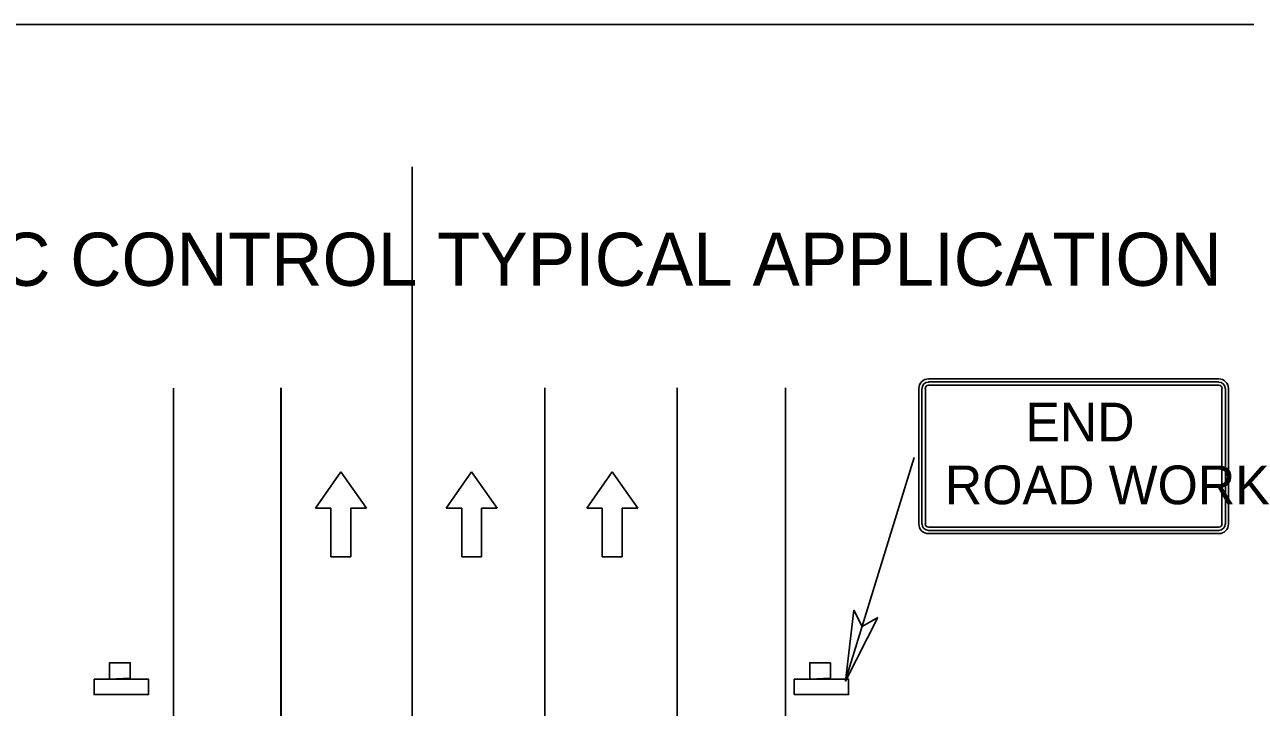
# Model space of a CAD drawing. Extents: x 0 to 1549163, y -476626 to 622136.
# Drawn here: x 15.545 to 18.03, y 15.278 to 16.667 of the extents above; entities that cross this region are included whole.
import ezdxf

# ---------------------------------------------------------------- set-up
doc = ezdxf.new("R2010")
doc.units = 0
for name, color, linetype in [('C-SIGN-FACE-N', 7, 'Continuous'), ('DETL-DIMS', 7, 'Continuous'), ('DETL-LINE', 7, 'Continuous'), ('DETL-TITL', 7, 'Continuous'), ('USER-BORD', 7, 'Continuous'), ('USER-CLIP', 7, 'Continuous')]:
    doc.layers.add(name, color=color, linetype=linetype)

# ---------------------------------------------------------------- blocks, each defined once
blk = doc.blocks.new('SIGN15')
at = {"layer": 'USER-BORD'}
for points in [[(-0.0013, 0.0018), (0.0011, 0.0019), (0.0011, 0.0037), (-0.0013, 0.0037)], [(-0.0031, 0.0018), (-0.0031, 0), (0.0032, 0), (0.0032, 0.0018)]]:
    blk.add_lwpolyline(points, close=True, dxfattribs=at)
blk = doc.blocks.new('TD')
at = {"layer": 'USER-BORD'}
for p, q in [((0, 0), (-0.0054, -0.0077)), ((0, 0), (0.0054, -0.0077)), ((-0.0054, -0.0077), (-0.0021, -0.0077)), ((-0.0021, -0.018), (-0.0021, -0.0077)), ((0.0021, -0.018), (0.0021, -0.0077)), ((0.0054, -0.0077), (0.0021, -0.0077)), ((-0.0002, -0.018), (-0.0021, -0.018)), ((-0.0002, -0.018), (0.0002, -0.018)), ((0.0002, -0.018), (0.0021, -0.018))]:
    blk.add_line(p, q, dxfattribs=at)

msp = doc.modelspace()

# ---------------------------------------------------------------- linework, layer by layer
at = {"layer": 'C-SIGN-FACE-N'}
for p, q in [((17.365, 15.6509), (17.365, 15.9269)), ((17.3713, 15.6509), (17.3713, 15.9269)), ((17.3783, 15.6509), (17.3783, 15.9269)), ((17.3846, 15.9464), (17.9755, 15.9464)), ((17.3846, 15.9464), (17.9755, 15.9464)), ((17.3846, 15.9401), (17.9755, 15.9401)), ((17.3846, 15.9332), (17.9755, 15.9332)), ((17.9818, 15.9269), (17.9818, 15.6509)), ((17.9887, 15.9269), (17.9887, 15.6509)), ((17.995, 15.9269), (17.995, 15.6509)), ((17.9755, 15.6446), (17.3846, 15.6446)), ((17.9755, 15.6377), (17.3846, 15.6377)), ((17.9755, 15.6314), (17.3846, 15.6314))]:
    msp.add_line(p, q, dxfattribs=at)
for centre, radius, start, end in [((17.3847, 15.9267), 0.0197, 90, 180), ((17.3847, 15.9267), 0.0131, 90, 180), ((17.3847, 15.9267), 0.00656, 90, 180), ((17.9753, 15.9267), 0.0197, 360, 90), ((17.9753, 15.9267), 0.0131, 360, 90), ((17.9753, 15.9267), 0.00656, 360, 90), ((17.3847, 15.6511), 0.0197, 180, 270), ((17.3847, 15.6511), 0.0131, 180, 270), ((17.3847, 15.6511), 0.00656, 180, 270), ((17.9753, 15.6511), 0.0197, 270, 360), ((17.9753, 15.6511), 0.0131, 270, 360), ((17.9753, 15.6511), 0.00656, 270, 360)]:
    msp.add_arc(centre, radius, start, end, dxfattribs=at)
at = {"layer": 'DETL-DIMS'}
for p, q in [((17.2162, 15.3355), (17.3558, 15.7866)), ((17.216, 15.3315), (17.233, 15.4756)), ((17.216, 15.3315), (17.2815, 15.461)), ((17.2494, 15.4425), (17.233, 15.4756)), ((17.2815, 15.461), (17.2494, 15.4425))]:
    msp.add_line(p, q, dxfattribs=at)
msp.add_lwpolyline([(17.2815, 15.461), (17.216, 15.3315), (17.233, 15.4756), (17.2494, 15.4425)], close=True, dxfattribs=at)
at = {"layer": 'DETL-LINE'}
for p, q in [((16.3341, 16.3778), (16.3341, 8.4351)), ((15.8482, 15.9277), (15.8482, 7.985)), ((16.0672, 15.9278), (16.0672, 7.9851)), ((16.0673, 15.9277), (16.0673, 7.985)), ((16.3341, 15.9278), (16.3341, 7.9851)), ((16.6039, 15.9278), (16.6039, 7.9851)), ((16.6039, 15.9278), (16.6039, 7.9851)), ((16.8736, 15.9278), (16.8736, 7.9851)), ((17.0935, 15.9278), (17.0935, 7.9851)), ((16.6039, 15.8673), (16.6039, 7.9246))]:
    msp.add_line(p, q, dxfattribs=at)
for points in [[(16.3342, 15.9277), (16.3342, 15.8715)], [(16.604, 15.9277), (16.604, 15.8715)], [(16.3342, 15.534), (16.3342, 15.4777)], [(16.604, 15.534), (16.604, 15.4777)], [(16.3342, 15.4777), (16.3342, 15.4215)], [(16.604, 15.4777), (16.604, 15.4215)]]:
    msp.add_lwpolyline(points, dxfattribs=at)
at = {"layer": 'USER-CLIP'}
msp.add_lwpolyline([(19.9377, 16.6675), (11.4377, 16.6675), (11.4377, 5.6675), (19.9377, 5.6675)], close=True, dxfattribs=at)

# ---------------------------------------------------------------- block references
at = {"layer": 'DETL-LINE'}
for name, p, xscale, yscale in [('TD', (16.1891, 15.7573), 9.6, 9.6), ('TD', (16.455, 15.7573), 9.6, 9.6), ('TD', (16.7411, 15.7573), 9.6, 9.6), ('SIGN15', (15.7413, 15.304), 17.523809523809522, 17.523809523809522), ('SIGN15', (17.166, 15.304), 17.523809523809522, 17.523809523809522)]:
    msp.add_blockref(name, p, dxfattribs=dict(at, xscale=xscale, yscale=yscale))

# ---------------------------------------------------------------- texts
at = {"layer": 'C-SIGN-FACE-N'}
for s, p in [('END', (17.5817, 15.8192)), ('ROAD WORK', (17.4179, 15.6913))]:
    msp.add_text(s, height=0.07875, rotation=360, dxfattribs=at).set_placement(p)
at = {"layer": 'DETL-TITL'}
msp.add_text('TEMPORARY TRAFFIC CONTROL TYPICAL APPLICATION', height=0.108, dxfattribs=at).set_placement((14.0336, 16.1357))

doc.saveas('drawing.dxf')
